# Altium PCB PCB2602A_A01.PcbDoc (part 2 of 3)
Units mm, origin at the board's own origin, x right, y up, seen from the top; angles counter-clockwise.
Board outline 30.4 x 45.4 mm, 8 copper layers (Top Layer, Signal Layer 2, Signal Layer 3, Signal Layer 4, Signal Layer 5, Signal Layer 6, Signal Layer 7, Bottom Layer), stack 1.594 mm thick; 180 components, 124 nets, 679 pads, 487 vias.
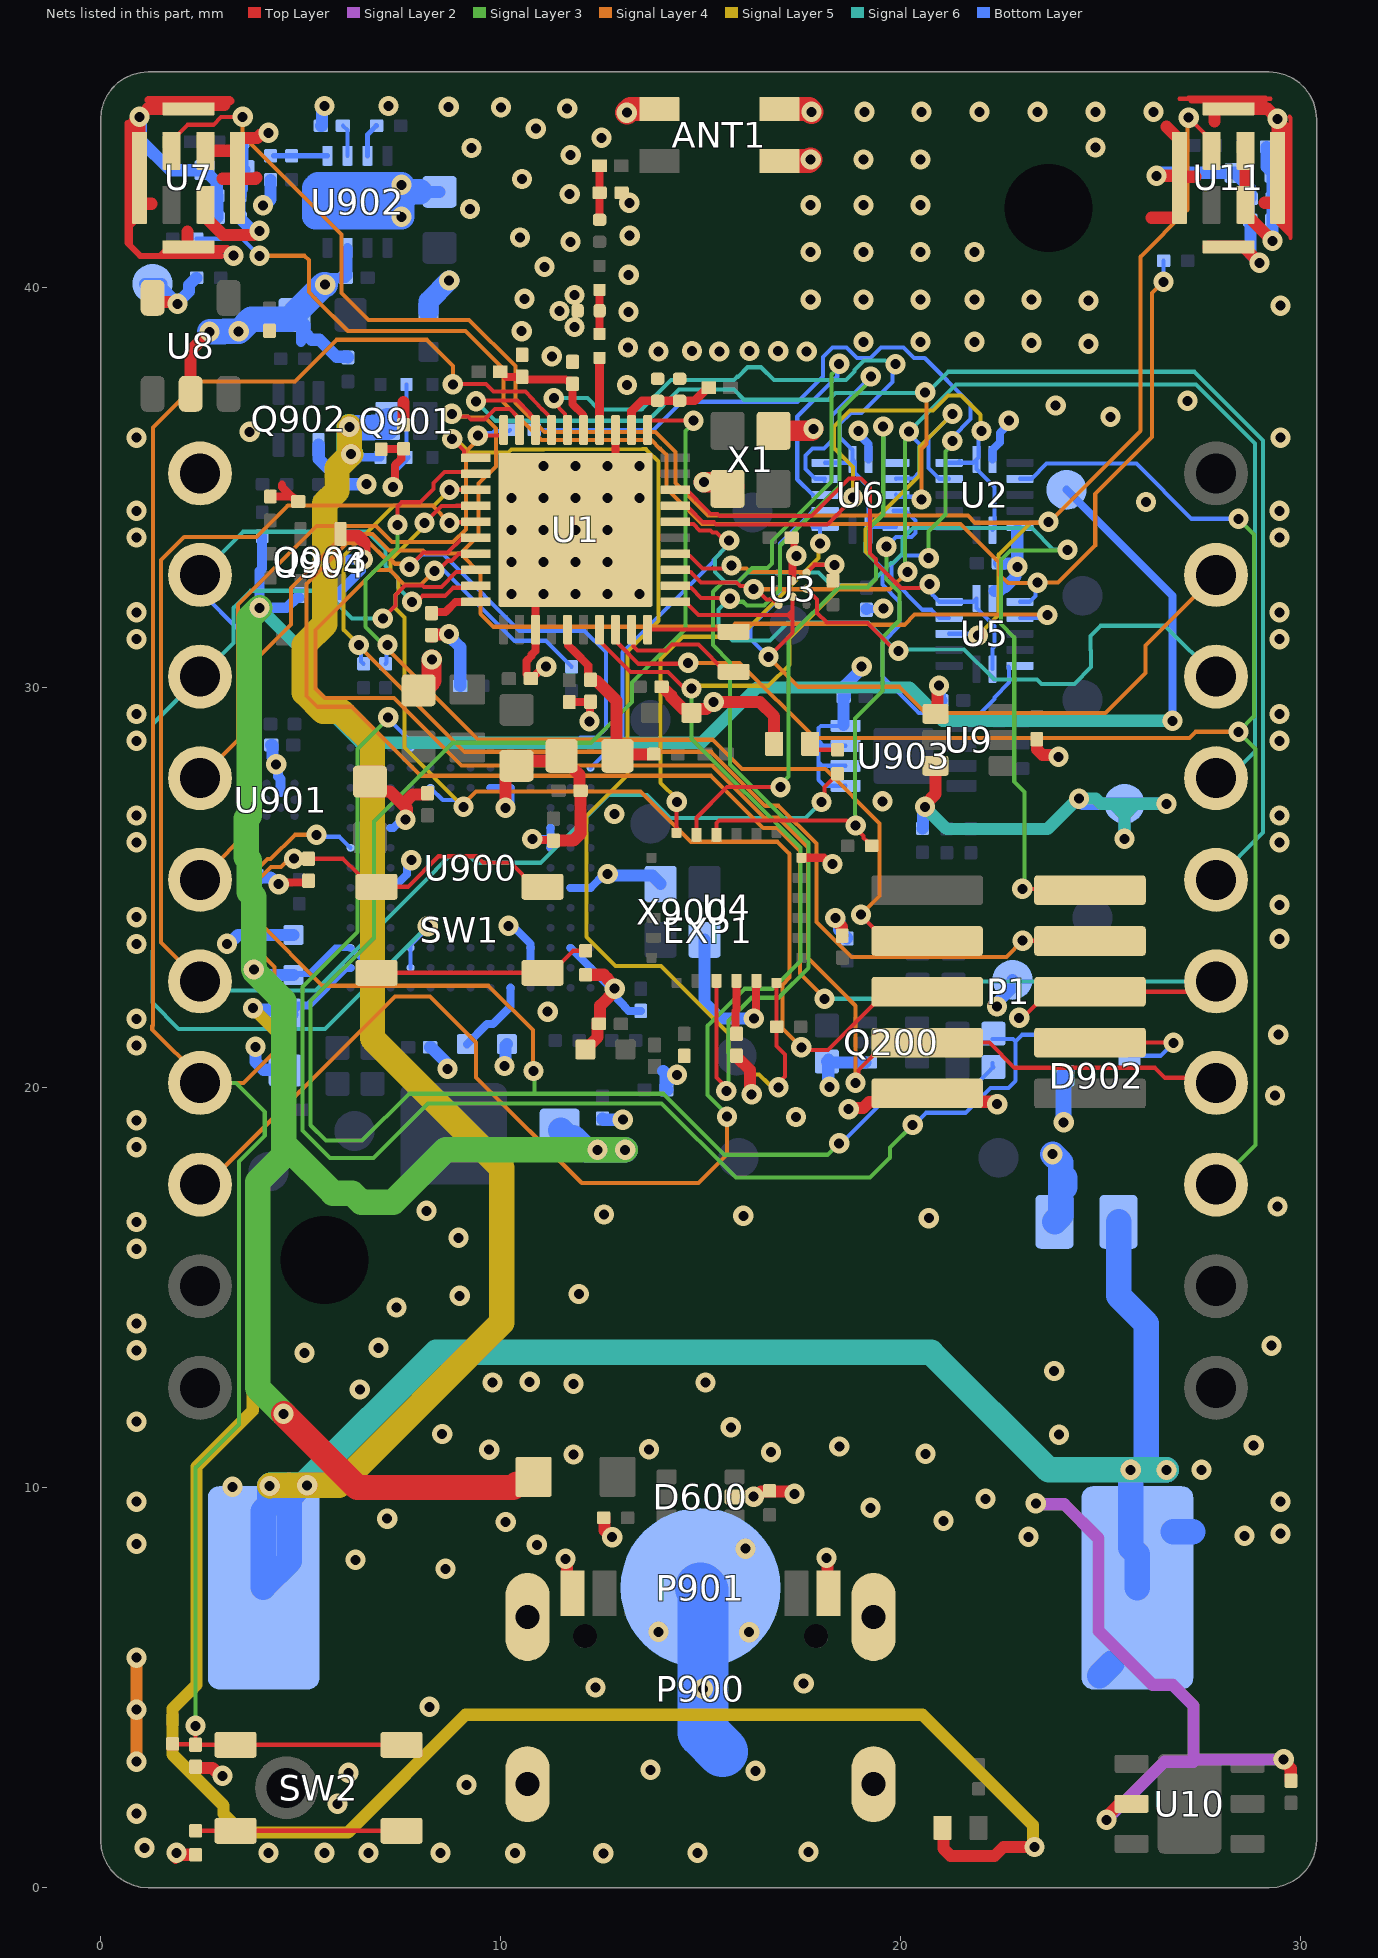
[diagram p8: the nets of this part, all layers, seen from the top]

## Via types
v1: diameter 0.508, hole 0.25, Top Layer to Bottom Layer, tented both sides, 475 vias
v2: diameter 0.5, hole 0.25, Top Layer to Bottom Layer, tented both sides, 12 vias

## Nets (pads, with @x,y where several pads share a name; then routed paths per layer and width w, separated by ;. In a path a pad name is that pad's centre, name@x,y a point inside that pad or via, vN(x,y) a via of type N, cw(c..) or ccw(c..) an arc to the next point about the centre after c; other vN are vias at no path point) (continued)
DBG_PTI_FRAME: P1.9 U1.6 U900.N2 | length 31.9
  Top Layer w0.102: U1.6@14.37,34.15 14.429,34.091 14.822,34.091 14.978,33.934 15.252,33.934 15.303,33.883 15.402,33.883 15.605,33.68 v1(15.715,33.68) ; v1(23.045,24.972) 25.053,24.972 P1.9@25.085,24.94
  Signal Layer 3 w0.102: v1(23.045,24.972) 23.104,25.031 23.104,27.396 22.841,27.659 22.841,31.263 22.512,31.592 22.512,33.193 22.75,33.432 23.982,33.432 v1@24.025,33.475
  Signal Layer 6 w0.102: v1(15.715,33.68) 15.715,33.588 15.49,33.363 15.49,33.359 15.359,33.228 15.359,32.896 15.62,32.635 15.925,32.635 16.171,32.881 17.943,32.881 18.256,32.568 19.213,32.568 19.764,33.119 19.812,33.119 20.05,33.357 20.05,33.73 20.313,33.993 23.282,33.993 23.825,33.45 v1(24.175,33.45)
  Bottom Layer w0.102: U900.N2@12.25,28 13.054,28.804 13.054,30.729 13.054,30.887 14.193,32.026 ; 14.193,32.027 15.329,33.162 15.329,33.198 15.49,33.359 15.49,33.371 15.715,33.596 v1(15.715,33.68)
DBG_RESET: D902.1 P1.3 R206.1 R209.2 U900.D1 | length 40.5
  Top Layer w0.1: v1@26.82,21.13 v1(26.825,21.125)
  Top Layer w0.102: P1.3@25.085,21.13 v1@26.82,21.13
  Signal Layer 3 w0.102: v1(7.192,29.26) 7.192,29.231 6.425,28.464 6.425,23.9 5.05,22.525 5.05,18.928 5.732,18.246 6.821,18.246 8.184,19.609 14.029,19.609 15.881,17.756 19.238,17.756 19.732,18.251 19.732,18.502 v1(20.305,19.074)
  Bottom Layer w0.102: v1(7.192,29.26) 7.192,29.231 7.75,28.672 U900.D1@7.75,28.5 ; v1(20.305,19.074) 20.33,19.074 20.631,19.375 21.623,19.375 22.246,19.998 22.698,19.998 22.875,20.175 22.875,21.162 ; R209.2@22.298,21.222 22.815,21.222 22.875,21.162 ; v1(26.825,21.125) 26.5,20.8 D902.1@25.725,20.8 25.2,21.325 23.038,21.325 22.875,21.162
DBG_SWCLK: P1.8 R920.2 U1.22 | length 25.6
  Top Layer w0.102: v1(7.425,34.075) 7.425,34.537 7.525,34.637 7.987,34.637 8.319,34.969 8.319,35.118 8.599,35.399 9.331,35.399 U1.22@9.38,35.35 ; v1(19.012,24.327) 19.012,24.31 19.653,23.67 P1.8@20.665,23.67
  Signal Layer 3 w0.102: v1(7.175,31.075) 7.068,31.075 6.619,31.525 6.619,32.693 7.425,33.5 v1(7.425,34.075)
  Signal Layer 4 w0.102: v1(7.175,31.075) 7.175,30.968 9.443,28.7 15.306,28.7 16.039,27.967 18.119,27.967 19.475,26.611 19.475,24.789 v1(19.012,24.327)
  Bottom Layer w0.102: R920.2@7.125,30.6 7.15,30.625 7.15,31.05 v1(7.175,31.075)
DBG_SWDIO: P1.7 R919.2 U1.23 | length 29.7
  Top Layer w0.102: v1(8.725,34.95) U1.23@9.38,34.95 ; v1(23.053,23.676) 24.729,23.676 P1.7@24.735,23.67
  Signal Layer 4 w0.102: v1(6.455,31.069) 6.455,31.045 9.1,28.4 15.267,28.4 16.617,27.05 16.95,27.05 17.893,26.107 17.893,24.145 18.772,23.266 22.643,23.266 v1(23.053,23.676)
  Signal Layer 5 w0.102: v1(6.455,31.069) 6.074,31.451 6.074,33.298 6.618,33.843 7.332,34.556 8.331,34.556 v1(8.725,34.95)
  Bottom Layer w0.102: v1(6.455,31.069) 6.515,31.01 6.515,30.66 R919.2@6.575,30.6
DBG_SWO: P1.6 U1.24 U900.E3 | length 28.6
  Top Layer w0.102: v1(8.1,34.125) 8.519,34.544 8.893,34.544 8.9,34.55 U1.24@9.38,34.55 ; v1(17.517,21.009) 17.579,20.948 18.188,20.948 18.96,21.72 19.64,22.4 P1.6@20.665,22.4
  Signal Layer 4 w0.102: v1@9.037,27.063 9.381,27.406 13.501,27.406 14.757,26.15 16.925,26.15 17.225,25.85 17.225,22.755 17.044,22.574 17.044,21.483 v1(17.517,21.009)
  Signal Layer 5 w0.102: v1(8.1,34.125) 8.1,34.05 7.244,33.194 7.244,32.931 7.318,32.856 7.318,32.855 7.45,32.723 7.45,32.388 7.379,32.317 7.379,31.98 7.598,31.761 7.598,29.062 7.595,29.059 7.595,28.505 v1(9.075,27.025)
  Bottom Layer w0.102: U900.E3@8.25,27.5 8.555,27.195 8.905,27.195 v1(9.075,27.025)
DBG_VBUS: C901.1 D901.2 L901.2 R917.1 TPJ12.1 U900.A11 U900.B12 U904.5 | length 78.6
  Top Layer w0.635: v1(4.575,11.85) 6.418,10.007 10.321,10.007 10.406,10.092 10.692,10.092 10.825,10.225 L901.2@10.825,10.275
  Signal Layer 3 w0.635: v1(3.975,32) 3.718,31.743 3.718,26.805 3.643,26.731 3.643,25.767 3.718,25.693 3.718,24.891 3.833,24.776 v1(3.833,22.958) 3.85,22.975 3.85,22.902 4.575,22.177 4.575,18.3 3.928,17.654 3.928,12.497 v1(4.575,11.85) ; 4.725,18.45 5.808,17.367 6.291,17.367 6.517,17.141 7.316,17.141 8.625,18.45 v1(12.425,18.45) 12.427,18.448 v1(13.117,18.448)
  Signal Layer 6 w0.305: v1(3.975,32) 5,30.975 5,30.117 6.492,28.625 15.026,28.625 16,29.599 16,29.6 16.408,30.008 20.223,30.008 21.056,29.175 v1(26.8,29.175)
  Bottom Layer w0.152: C901.1@4.824,22.822 4.85,22.848 5.214,22.848 5.866,23.5 U900.A11@6.25,23.5 U900.B12@6.75,23
  Bottom Layer w0.203: TPJ12.1@24.15,34.95 26.8,32.3 v1(26.8,29.175)
  Bottom Layer w0.254: R917.1@4.04,33.787 4.04,32.98 3.975,32.915 v1(3.975,32) 4.65,32 4.902,32.252 U904.5@4.973,32.252
  Bottom Layer w0.305: v1(3.833,22.958) 3.888,22.958 4.025,22.822 C901.1@4.824,22.822
  Bottom Layer w0.635: D901.2@11.5,18.94 11.683,18.758 11.817,18.758 12.125,18.45 v1(12.425,18.45) 12.427,18.448 v1(13.117,18.448)
DBG_VCOM_CTS: EXP1.3 R922.2 U1.29 | length 10.7
  Top Layer w0.102: v1(7.785,32.148) 7.895,32.148 8.047,32.3 8.607,32.3 8.807,32.5 9.33,32.5 U1.29@9.38,32.55
  Signal Layer 6 w0.102: EXP1.3@2.486,32.82 3.566,33.9 6.675,33.9 7.125,33.45 7.125,33.046 7.432,32.74 7.432,32.502 v1(7.785,32.148)
  Bottom Layer w0.102: EXP1.3@2.486,32.82 2.486,32.415 3.5,31.401 R922.2@3.776,31.401
DBG_VCOM_RTS: EXP1.5 U1.28 U900.D11 U900.D12 | length 27.4
  Top Layer w0.102: v1(7.056,31.733) 7.375,32.053 7.375,32.314 7.616,32.555 8.049,32.555 8.086,32.518 8.518,32.518 8.891,32.891 9.321,32.891 U1.28@9.38,32.95
  Signal Layer 6 w0.102: v1(7.056,31.733) 6.287,31.733 5.596,32.425 3.75,32.425 3.325,32 3.325,31.119 EXP1.5@2.486,30.28 1.307,29.101 1.307,23.427 1.3,23.42 1.3,22.128 1.954,21.474 5.612,21.474 v1(8.176,24.038)
  Bottom Layer w0.102: U900.D12@7.75,23 U900.D11@7.75,23.5 7.75,23.562 v1@8.226,24.038
DBG_VCOM_RX: EXP1.14 P1.4 R921.2 U1.27 | length 41.2
  Top Layer w0.102: v1(8.35,32.925) 8.426,32.925 8.676,33.175 8.775,33.175 8.95,33.35 U1.27@9.38,33.35 ; v1(18.875,20.125) 18.953,20.202 18.953,20.443 19.64,21.13 22.22,21.13 22.85,20.5 26.366,20.5 26.616,20.25 27.756,20.25 EXP1.14@27.886,20.12
  Signal Layer 4 w0.102: 6.8,32.875 5.368,31.443 5.368,29.982 5.607,29.743 7.338,29.743 9.025,28.056 15.291,28.056 16.598,26.75 16.95,26.75 17.69,26.01 17.69,23.239 18.481,22.447 18.481,22.444 18.875,22.051 v1@18.875,20.127 ; 6.803,32.872 6.872,32.94 7.231,32.94 7.586,32.585 8.01,32.585 v1(8.35,32.925)
  Bottom Layer w0.102: v1@8.475,33.05 10.35,31.175 11.135,31.175 11.775,30.535 R921.2@11.775,30.525
DBG_VCOM_TX: EXP1.12 P1.5 U1.26 U900.L2 U900.M1 | length 50.9
  Top Layer w0.102: v1(7.725,33.023) 7.725,33.025 8.079,33.379 8.679,33.379 9.05,33.75 U1.26@9.38,33.75 ; v1(22.967,21.749) 23.046,21.749 23.698,22.4 27.626,22.4 EXP1.12@27.886,22.66
  Signal Layer 4 w0.102: v1(7.725,33.023) 7.647,33.101 7.358,33.101 7.233,33.226 7.117,33.226 6.728,33.615 6.165,33.615 5.15,32.6 5.15,29.8 5.425,29.525 6.281,29.525 8.006,27.8 15.26,27.8 16.567,26.493 16.907,26.493 17.486,25.914 17.486,22.853 18.1,22.239 v1(18.1,22.225)
  Signal Layer 6 w0.102: v1(18.1,22.225) 19.762,22.225 20.197,22.66 EXP1.12@27.886,22.66
  Bottom Layer w0.102: v1(7.725,33.023) 7.725,33.025 8.032,33.332 8.568,33.332 8.732,33.168 10.475,31.425 12.1,31.425 12.632,30.893 12.632,28.982 12.403,28.753 12.003,28.753 U900.M1@11.75,28.5 U900.L2@11.25,28
DBG_VREGO: C902.1 LED900.1 U900.A12 | length 51.6
  Top Layer w0.3: LED900.1@21.05,1.5 21.074,1.476 21.074,0.976 21.25,0.8 22.351,0.8 22.568,1.018 v1(23.35,1.018)
  Signal Layer 5 w0.3: 22.187,2.687 23.31,1.565 23.31,1.057 v1(23.35,1.018)
  Signal Layer 5 w0.305: v1(3.809,21.991) 4.7,21.1 4.7,18.425 3.805,17.53 3.805,11.93 2.4,10.525 2.4,5.075 1.8,4.475 1.8,3.331 3.075,2.056 3.075,1.85 3.542,1.383 6.183,1.383 9.125,4.325 20.55,4.325 22.187,2.687
  Bottom Layer w0.2: C902.1@4.8,21.833 4.8,21.903 4.95,22.053 5.195,22.053 6.142,23 U900.A12@6.25,23
  Bottom Layer w0.305: v1(3.809,21.991) 3.848,21.952 4.506,21.952 C902.1@4.625,21.833 C902.1@4.8,21.833
EFR32_BUTTON0: C38.1 EXP1.13 R25.2 SW2.1 SW2.2 U1.17 U900.A6 | length 63.3
  Top Layer w0.1: v1(8.806,37.588) 9.637,37.588 9.819,37.406 10.62,37.406 11.035,36.964 ccw(c11.331,37.241) 11.045,36.953 11.156,36.843 11.215,36.784 11.215,36.505 U1.17@11.275,36.445
  Top Layer w0.102: R25.2@1.8,3.6 1.812,3.588 2.362,3.588 C38.1@2.375,3.575 ; v1(2.375,4.05) C38.1@2.375,3.575 ; SW2.2@7.525,3.575 SW2.1@3.375,3.575 C38.1@2.375,3.575
  Signal Layer 3 w0.102: v1(2.375,4.05) 2.375,10.5 3.459,11.584 3.459,18.159 4.105,18.805 4.105,19.395 3.38,20.12 EXP1.13@2.486,20.12
  Signal Layer 4 w0.102: v1(5.4,26.325) 4.858,26.325 4.252,25.719 4.176,25.719 3.675,25.218 3.675,23.691 4.35,23.016 4.35,20.9 3.57,20.12 EXP1.13@2.486,20.12 2.486,20.264 1.292,21.458 1.292,21.542 1.306,21.557 1.306,36.504 2.458,37.656 4.857,37.656 5.902,38.7 7.811,38.7 8.157,38.7 8.812,38.045 8.812,37.594 v1(8.806,37.588)
  Bottom Layer w0.102: v1@5.4,26.275 5.975,26.275 U900.A6@6.25,26
EFR32_I2C_SCL: EXP1.15 U1.37 U2.4 | length 48.6
  Top Layer w0.102: U1.37@12.475,31.17 13.248,30.397 14.185,30.397 14.357,30.225 14.648,29.934 14.728,29.934 v1(14.775,29.981)
  Signal Layer 3 w0.102: v1(14.775,29.981) 14.775,28.725 17.496,26.004 17.496,23.171 16.8,22.475 16.1,22.475 15.175,21.55 15.175,19.815 15.66,19.331 v1(15.66,19.277)
  Signal Layer 4 w0.102: EXP1.15@2.486,17.58 2.655,17.58 7.356,22.281 8.238,22.281 9.382,21.137 9.382,20.262 12.029,17.614 14.944,17.614 15.66,18.33 v1(15.66,19.277)
  Signal Layer 5 w0.102: v1(14.775,29.981) 14.845,30.051 16.701,30.051 17.225,30.575 17.225,31.25 18.525,32.55 19.212,32.55 19.381,32.719 19.381,33.143 19.334,33.19 19.334,33.194 19.125,33.403 19.125,33.953 20.475,35.303 20.475,36.025 v1(21.298,36.848)
  Bottom Layer w0.102: v1(14.775,29.981) 14.775,30.025 v1@14.8,30.05 ; U2.4@21.215,35.225 20.975,35.225 20.827,35.373 20.824,35.373 20.7,35.496 20.7,36.25 v1(21.298,36.848)
EFR32_I2C_SDA: EXP1.16 U1.38 U2.9 | length 40.4
  Top Layer w0.102: U1.38@12.875,31.176 13.013,31.038 13.451,30.6 14.667,30.6 v1(14.691,30.624)
  Signal Layer 3 w0.102: EXP1.16@27.886,17.58 28.875,18.569 28.875,28.475 v1(28.45,28.9) 28.838,29.288 28.838,33.837 v1(28.45,34.225)
  Signal Layer 4 w0.102: v1(14.691,30.624) 15.976,30.624 17.856,28.744 27.219,28.744 27.375,28.9 v1(28.45,28.9)
  Bottom Layer w0.102: U2.9@22.985,35.225 23.275,35.225 23.652,35.602 25.898,35.602 27.275,34.225 v1(28.45,34.225)
EFR32_IMU_ENABLE: U1.16 U5.12 U6.5 U6.6 U6.12 U6.13 | length 25.5
  Top Layer w0.102: v1(11.331,37.241) 11.331,37.131 11.616,36.846 11.616,36.504 U1.16@11.675,36.445
  Signal Layer 6 w0.102: v1(11.331,37.241) 12.172,37.241 12.452,36.961 13.529,36.961 14.262,37.694 15.834,37.694 15.915,37.775 15.938,37.775 16.176,38.013 16.513,38.013 16.832,37.694 18.634,37.694 18.849,37.909 18.849,37.949 19.087,38.187 19.613,38.187 19.631,38.168 19.798,38.168 v1(19.875,38.091)
  Bottom Layer w0.102: U6.5@18.115,35.625 U6.6@18.751,35.625 ; U6.6@18.8,35.71 18.8,35.95 18.49,36.26 18.49,36.602 18.763,36.875 19.025,36.875 19.798,37.648 19.798,38.013 v1(19.875,38.091) ; U6.6@18.805,35.705 18.849,35.661 18.849,35.376 19.217,35.008 19.217,34.597 19.2,34.58 U6.13@19.2,33.976 ; U6.12@19.885,34.025 19.249,34.025 U6.13@19.2,33.976 ; U5.12@22.7,30.525 22.716,30.509 22.716,30.128 22.346,29.759 22.346,29.722 21.997,29.372 20.455,29.372 19.544,30.284 19.544,31.125 19.975,31.556 19.975,32.15 19.544,32.581 19.544,32.984 19.125,33.403 19.125,33.625 19.2,33.7 U6.13@19.2,33.976
EFR32_IMU_INT: R14.2 U1.21 U4.12 | length 28.2
  Top Layer w0.1: v1(8.788,36.22) 9.081,35.927 9.081,35.81 9.141,35.75 U1.21@9.38,35.75
  Top Layer w0.102: U4.12@16.9,22.53 R14.2@16.9,21.525 16.9,21.046 17.111,20.835 17.111,20.283 16.948,20.12 v1(16.948,20.01)
  Signal Layer 5 w0.1: v1(8.788,36.22) 8.89,36.22 9.223,35.888 10.201,35.888 10.269,35.956 11.073,35.956 13.55,35.966 13.633,35.966 13.663,35.937 13.945,35.655
  Signal Layer 5 w0.102: 13.945,35.655 13.945,31.675 13.175,30.905 13.175,27.825 12.15,26.8 12.15,23.775 12.877,23.048 14.006,23.048 15.7,21.354 15.7,20.875 16.244,20.331 16.463,20.331 16.706,20.088 16.87,20.088 v1(16.948,20.01)
EFR32_LED0: EXP1.11 R27.1 U1.25 | length 39
  Top Layer w0.102: v1(8.725,34.125) 8.737,34.137 9.367,34.137 U1.25@9.38,34.15 ; v1(18.023,27.143) 18.1,27.221 18.1,27.515 18.425,27.84 R27.1@18.425,27.85
  Signal Layer 4 w0.102: EXP1.11@2.486,22.66 1.51,23.636 1.51,33.191 2.091,33.772 3.896,33.772 4.68,34.556 8.294,34.556 v1(8.725,34.125)
  Signal Layer 6 w0.102: EXP1.11@2.891,22.66 EXP1.11@2.486,22.66 2.713,22.433 5.292,22.433 5.377,22.433 8.385,25.441 8.385,25.46 8.713,25.788 9.237,25.788 9.4,25.625 10.995,25.625 12.694,27.324 13.657,27.324 14.238,26.744 17.624,26.744 v1(18.023,27.143)
EFR32_MIC_ENABLE: U1.8 U5.5 U5.6 U5.13 | length 12.9
  Top Layer w0.102: U1.8@14.37,34.95 14.429,34.891 14.709,34.891 14.893,34.707 14.893,34.691 15.243,34.341 15.42,34.341 15.472,34.29 17.77,34.29 18.712,35.232 19.015,35.232 19.237,35.01 19.237,33.357 19.382,33.213 19.382,33.118 19.768,32.732 20.007,32.493 20.464,32.493 20.481,32.511 20.649,32.511 v1(20.726,32.588)
  Signal Layer 4 w0.102: v1@20.614,32.511 20.632,32.493 v1(20.726,32.588)
  Bottom Layer w0.1: v1(20.726,32.588) 20.804,32.51 20.804,32.323 20.852,32.276
  Bottom Layer w0.102: 20.852,32.276 20.978,32.15 U5.5@21.215,32.15 21.815,32.15 U5.6@21.9,32.235 21.9,31.991 22.35,31.541 22.35,31.028 22.3,30.978 U5.13@22.3,30.465
EFR32_PB0: EXP1.7 R16.2 U1.20 | length 15.6
  Top Layer w0.1: v1(9.43,36.302) 10.015,36.302 10.015,36.305 10.075,36.365 U1.20@10.075,36.445
  Signal Layer 4 w0.1: EXP1.7@2.486,27.74 3.438,28.692 3.438,32.08 5.402,34.045 6.021,34.045 6.881,34.045 7.287,33.639 8.813,33.639 9.131,33.957 9.131,35.902 9.43,36.202 v1(9.43,36.302)
  Bottom Layer w0.1: v1(9.43,36.302) 9.5,36.372 9.798,36.372 9.851,36.424 10.216,36.424 R16.2@10.241,36.449
EFR32_PC0: EXP1.4 U1.1 U3.D2 U6.2 | length 22.9
  Top Layer w0.102: U1.1@14.605,32.175 14.689,32.091 14.689,32.077 14.949,31.818 17.183,31.818 ; v1(16.7,30.775) 17.3,31.375 17.3,31.7 ; U3.D2@17.3,32.275 17.3,31.935 ; 17.183,31.818 17.3,31.7 ; 17.183,31.818 17.3,31.935 ; 17.3,31.7 17.3,31.935
  Signal Layer 4 w0.102: v1(16.7,30.775) 17.45,30.025 19.975,30.025 20.628,29.372 25.127,29.372 26.125,30.371 26.125,31.059 EXP1.4@27.886,32.82
  Bottom Layer w0.102: v1(16.7,30.775) 16.25,31.225 16.25,31.523 16.758,32.031 ; 16.759,32.032 16.985,32.257 16.985,33.605 U6.2@17.805,34.425
EFR32_PC1: EXP1.6 U1.2 U3.C3 U6.4 | length 32.1
  Top Layer w0.102: U1.2@14.37,32.55 14.429,32.491 14.773,32.491 15.016,32.247 15.711,32.247 v1(15.73,32.228) ; U3.C3@17.65,32.475 17.916,32.209 17.916,31.873 18.155,31.633 19.167,31.633 19.875,30.925 v1(19.95,30.925)
  Signal Layer 3 w0.102: v1(15.73,32.228) 15.808,32.151 16.066,32.151 16.16,32.057 16.592,32.057 16.985,32.45 16.985,33.551 18.478,35.044 18.478,36.919 19.256,37.696 v1(19.256,37.78)
  Signal Layer 6 w0.102: v1(15.73,32.228) 15.725,32.228 15.45,31.953 15.45,31.525 15.794,31.181 16.731,31.181 17.175,31.625 19.2,31.625 19.9,30.925 v1(19.95,30.925) 19.981,30.956 21.59,30.956 22.343,30.204 23.416,30.204 23.522,30.098 24.348,30.098 24.765,30.515 24.765,30.927 24.745,30.947 24.745,31.295 25,31.55 26.616,31.55 EXP1.6@27.886,30.28
  Bottom Layer w0.102: U6.4@18.052,35.218 18.094,35.176 U6.4@18.098,35.176 ; U6.4@18.115,35.225 17.875,35.225 17.727,35.373 17.724,35.373 17.623,35.474 17.623,35.805 17.8,35.982 18.082,35.982 18.287,36.187 18.287,36.811 v1(19.256,37.78)
EFR32_PD0: U1.40 X2.1 | length 2.2
  Top Layer w0.102: U1.40@13.675,31.455 14.825,31.455 15.773,31.455 X2.1@15.828,31.4
EFR32_PD1: U1.39 X2.2 | length 3.3
  Top Layer w0.102: U1.39@13.275,31.455 13.325,31.405 13.325,31.028 13.42,30.933 14.138,30.933 14.284,31.079 14.949,31.079 15.628,30.4 X2.2@15.828,30.4
EFR32_PDM_CLK: R16.1 U5.4 | length 20.5
  Signal Layer 3 w0.102: v1(20.702,33.238) 20.702,33.91 21.125,34.333 21.125,35.908 21.294,36.076 v1(21.294,36.17)
  Bottom Layer w0.102: R16.1@10.841,36.449 12.875,36.449 13.824,36.449 14.525,37.15 17.425,37.15 18.059,37.784 18.059,38.268 18.297,38.506 18.644,38.506 18.907,38.244 19.243,38.244 19.506,38.507 20.069,38.507 20.332,38.244 20.604,38.244 21.752,37.096 21.752,36.719 21.294,36.261 v1(21.294,36.17) ; v1@20.626,33.238 v1(20.702,33.238) 20.634,33.306 20.007,33.306 19.769,33.068 19.769,32.731 20.55,31.95 20.771,31.95 20.971,31.75 U5.4@21.215,31.75
EFR32_PDM_DATA: EXP1.9 U1.19 U5.9 | length 37.1
  Top Layer w0.1: 9.86,36.967 10.241,36.967 10.337,36.871 10.337,36.853 10.415,36.774 10.415,36.505 U1.19@10.475,36.445
  Top Layer w0.102: v1(8.783,36.85) 8.849,36.783 9.189,36.783 9.264,36.708 9.602,36.708 9.86,36.967
  Signal Layer 4 w0.102: EXP1.9@2.486,25.2 3.9,26.614 3.9,30.725 4.76,31.585 4.76,32.498 6.105,33.843 6.797,33.843 7.211,33.429 8.066,33.429 8.139,33.356 8.994,33.356 ; v1(8.783,36.85) 8.849,36.783 9.189,36.783 9.22,36.753 9.615,36.753 9.882,36.486 9.882,35.535 9.45,35.102 9.45,33.813 8.994,33.356 ; v1(23.669,31.819) 23.66,31.829 20.354,31.829 20.101,31.575 19.218,31.575 19.193,31.6 15.859,31.6 15.784,31.525 9.825,31.525 9.5,31.85 9.5,32.85 8.994,33.356
  Bottom Layer w0.102: U5.9@22.985,31.75 23.6,31.75 v1(23.669,31.819)
EFR32_RESET: C1.1 R209.1 R212.2 SW1.1 SW1.2 U1.11 | length 63.5
  Top Layer w0.102: v1(4.834,25.727) C1.1@5.199,25.726 ; C1.1@5.2,25.725 6.061,25.725 6.435,25.351 6.435,25.298 6.708,25.025 SW1.1@6.9,25.025 7.685,25.025 8.448,25.788 9.403,25.788 9.559,25.632 10.243,25.632 10.85,25.025 SW1.2@11.05,25.025 SW1.2@11.3,24.775 ; U1.11@13.675,36.445 13.675,36.617 13.734,36.677 v1(14.823,36.677)
  Signal Layer 3 w0.102: v1(10.823,20.421) 10.85,20.395 10.85,19.85 ; v1(14.823,36.677) 14.823,36.617 14.62,36.414 14.62,31.471 13.284,30.134 13.284,29.643 12.266,28.625 8.796,28.625 6.83,26.66 6.83,23.743 5.253,22.166 5.253,19.063 5.637,18.679 6.536,18.679 7.707,19.85 10.808,19.85 10.85,19.85 ; v1(18.464,18.61) 18.459,18.61 18.174,18.325 15.6,18.325 14.075,19.85 10.85,19.85
  Signal Layer 4 w0.102: v1(4.834,25.727) 4.724,25.727 4.513,25.516 4.261,25.516 3.936,25.191 3.936,24.164 5.55,22.55 9.7,22.55 10.808,21.442 10.808,20.437 v1(10.823,20.421)
  Bottom Layer w0.102: v1(18.464,18.61) 18.509,18.61 19.649,19.75 21.557,19.75 22.25,20.443 R212.2@22.25,20.45 ; R212.2@22.298,20.622 22.298,20.498 22.314,20.514 R212.2@22.321,20.514
EFR32_SENSOR_ENABLE: U1.7 U2.5 U2.6 U2.13 | length 15.1
  Top Layer w0.102: U1.7@14.37,34.55 14.429,34.491 14.709,34.491 15.062,34.138 15.336,34.138 15.387,34.086 18.168,34.086 18.811,34.729 v1(18.811,34.755)
  Signal Layer 5 w0.102: v1(18.811,34.755) 18.811,35.521 18.331,36 18.331,36.531 18.737,36.937 20.812,36.937 21.183,37.308 21.517,37.308 22,36.825 22,36.444 v1(22.025,36.418)
  Bottom Layer w0.102: U2.5@21.215,35.625 21.815,35.625 U2.6@21.9,35.71 ; U2.5@21.425,35.625 U2.5@21.474,35.674 ; v1@22.025,36.327 v1(22.025,36.418) 21.949,36.342 21.949,35.759 U2.6@21.9,35.71 ; U2.13@22.3,33.94 22.35,33.99 22.35,35.016 21.9,35.466 U2.6@21.9,35.71
EFR32_SPI_FLASH_CS: R12.2 U1.4 U3.A3 | length 5.6
  Top Layer w0.102: U1.4@14.37,33.35 14.429,33.291 14.733,33.291 15.044,32.98 15.695,32.98 v1(15.772,33.057) ; U3.A3@17.65,32.875 17.85,33.075 v1(18.35,33.075) v1@18.375,33.075
  Top Layer w0.203: R12.2@18.307,32.685 R12.2@18.312,32.68 ; v1@18.355,33.07 v1(18.35,33.075) 18.331,33.056 18.331,32.699 R12.2@18.312,32.68 ; R12.2@18.37,32.611 18.312,32.67 R12.2@18.312,32.68
  Signal Layer 4 w0.102: v1(15.772,33.057) 15.85,32.98 16.144,32.98 16.23,32.893 17.643,32.893 17.824,33.075 v1(18.35,33.075)
EFR32_SPI_IMU_CS: EXP1.10 U1.18 U6.10 | length 38.2
  Top Layer w0.1: v1(9.388,37.159) 9.409,37.18 10.418,37.18 10.737,36.862 10.737,36.843 10.875,36.705 U1.18@10.875,36.445
  Signal Layer 4 w0.102: v1(20.521,34.708) 20.521,35.97 20.645,36.093 20.645,37.355 v1(20.615,37.385)
  Signal Layer 6 w0.102: v1(9.388,37.159) 9.872,36.675 13.68,36.675 14.459,37.455 15.832,37.455 16.086,37.2 18.203,37.2 18.377,37.374 20.604,37.374 v1(20.615,37.385) ; v1@20.645,37.355 21.189,37.9 27.35,37.9 29.066,36.184 29.066,26.38 EXP1.10@27.886,25.2
  Bottom Layer w0.102: U6.10@19.885,34.825 19.934,34.776 20.454,34.776 v1(20.521,34.708)
EFR32_SPI_SCLK: EXP1.8 U1.3 U3.E1 U6.9 | length 31.1
  Top Layer w0.102: U1.3@14.37,32.95 14.429,32.891 14.754,32.891 15.01,32.635 15.899,32.635 15.993,32.541 16.251,32.541 v1(16.329,32.463) ; v1@16.33,32.462 16.4,32.462 16.651,32.211 16.814,32.211 U3.E1@16.989,32.036
  Signal Layer 3 w0.102: v1(20.175,32.9) 20.115,32.96 20.115,36.2 20.209,36.295 v1(20.209,36.405)
  Signal Layer 4 w0.102: v1(16.329,32.463) 19.738,32.463 v1(20.175,32.9)
  Signal Layer 6 w0.102: v1(16.329,32.463) v1@16.344,32.448 ; v1(20.209,36.405) 21.386,37.581 27.381,37.581 28.856,36.106 28.856,28.407 28.19,27.74 EXP1.8@27.886,27.74
  Bottom Layer w0.102: U6.9@19.885,35.225 19.892,35.232 20.318,35.232 20.475,35.389 20.475,36.095 20.209,36.361 v1(20.209,36.405)
GND: ANT1.2 ANT1.3 ANT1.4 C1.2 C2.2 C4.2 C7.2 C8.2 C9.2 C11.2 C12.2 C13.2 C14.2 C15.2 C16.2 C18.2 C19.2 C20.2 C21.2 C22.2 C23.2 C24.2 C25.2 C26.2 C27.2 C28.2 C29.2 C30.2 C31.2 C32.2 C33.2 C34.2 C35.2 C36.2 C37.2 C38.2 C39.2 C900.2 C901.2 C902.2 C903.2 C904.2 C905.2 C907.2 C908.2 C909.2 C910.2 C911.2 C914.2 C915.2 C916.2 C917.2 C918.2 C919.2 C920.2 C921.2 C923.2 C924.2 C925.2 C926.2 C928.2 D600.2 D902.3 EXP1.1 LED1.2 P1.2 P900.A1_B12 P900.B1_A12 P900.S1 P900.S2 P900.S3 P900.S4 P901.2 Q200.1 Q902.1 Q903.1 R1.1 R26.2 R208.1 R620.1 R621.1 R909.1 R915.1 R933.2 R934.2 R937.2 TPJ13.1 U1.0 U1.13 U1.33 U2.7 U2.12 U3.B2 U4.11 U4.18 U5.7 U6.7 U7.3 U7.5 U7.6 U7.7 U7.8 U8.2 U9.1 U10.2 U11.5 U11.6 U11.7 U11.8 U900.C5 U900.C8 U900.H3 U900.J3 U900.K11 U900.K12 U900.L5 U900.L6 U900.M8 U900.M11 U900.N8 U900.N12 U901.B2 U902.3 U902.9 U903.1 U903.2 U903.3 U903.4 U904.2 U904.4 X1.2 X1.4 X900.2 X900.4 | length 185.4
  Top Layer w0.102: 26.975,44.725 27.175,44.725 ; 27.25,44.675 27.267,44.658 29.117,44.658 29.125,44.65 ; 29.125,44.75 27.2,44.75 27.175,44.725 ; 29.25,44.725 27.175,44.725 ; U11.8@29.412,41.638 29.75,41.3 ; 29.625,41.568 29.7,41.493 29.7,41.4 ; 29.725,44.275 29.75,44.25 29.75,41.3 ; 29.75,41.25 29.75,41.3
  Top Layer w0.15: 0.675,44.125 0.675,41.116 0.739,41.052 ; U7.6@0.975,42.75 0.975,42.16 0.975,41.788 0.739,41.551 0.739,41.052 ; U7.5@2.2,41.025 1.713,41.025 U7.5@1.556,40.869 ; 3,40.8 2.931,40.869 U7.5@1.556,40.869 ; 3.025,40.8 1.487,40.8 ; 0.739,41.052 0.991,40.8 1.487,40.8 ; 1.487,40.8 U7.5@1.556,40.869
  Top Layer w0.18: C25.2@17.275,33.75 17.335,33.69 17.335,33.36 v1(17.395,33.3)
  Top Layer w0.2: 1.2,44.7 3.225,44.7 3.25,44.675 ; v1@1.825,0.75 v1@1.875,0.7 ; U7.5@2.2,41.025 2.2,40.968 3.16,40.968 v1(3.325,40.802) ; R26.2@2.35,0.825 R26.2@2.375,0.8 ; v1(4.454,25.089) 4.497,25.132 5.157,25.132 C1.2@5.2,25.175 ; v1(10.795,26.22) 10.815,26.199 11.301,26.199 C925.2@11.321,26.179 ; 10.875,30.925 10.778,30.828 10.778,30.799 10.65,30.671 10.65,30.338 10.678,30.31 10.678,30.29 10.738,30.23 C9.2@10.758,30.23 10.778,30.23 11.074,30.526 v1(11.141,30.526) ; U1.33@10.875,31.455 U1.0@10.875,32.95 ; C13.2@11.719,29.643 11.722,29.647 C21.2@12.247,29.647 ; v1(12.225,29.159) 12.238,29.172 12.238,29.637 C21.2@12.247,29.647 ; C21.2@12.25,29.65 C21.2@12.247,29.647 ; U1.0@12.875,35.75 U1.13@12.875,36.445 ; U3.B2@17.3,32.675 17.3,33.121 17.395,33.217 v1(17.395,33.3)
  Top Layer w0.203: R937.2@4.244,34.781 C928.2@4.773,34.781 ; 4.534,35.075 4.534,35.02 C928.2@4.773,34.781 ; C928.2@4.943,34.656 4.923,34.656 4.827,34.752 4.802,34.752 C928.2@4.773,34.781 ; 10.875,30.925 U1.33@10.875,31.455 ; v1@12.22,29.164 v1(12.225,29.159) ; ANT1.4@13.972,44.378 ANT1.4@13.986,44.378 ; v1(16.332,21.732) 16.382,21.782 16.382,22.512 U4.11@16.4,22.53 ; U4.18@17.62,25.75 18.088,25.75 v1@18.244,25.593
  Top Layer w0.3: Q903.1@6,33.85 6,33.806 6.424,33.806 6.6,33.631 6.6,33.613 ; v1(6.559,33.209) 6.599,33.249 6.599,33.612 ; R915.1@7.575,36.575 7.575,37.143 ; v1(11.622,8.222) 11.662,8.182 11.662,7.498 P900.A1_B12@11.8,7.36 ; C903.2@12.119,20.956 12.428,21.264 12.428,21.59 12.438,21.6 C905.2@12.458,21.6 12.478,21.6 12.488,21.61 12.488,22.054 12.854,22.42 v1(12.854,22.477) ; R621.1@12.575,9.25 12.585,9.25 12.595,9.24 12.595,8.936 12.766,8.766 v1(12.791,8.766) ; v1(15.328,29.645) 16.48,29.645 16.841,29.284 LED1.2@16.841,28.6 ; D600.2@15.85,9.775 15.852,9.777 16.324,9.777 v1(16.326,9.779) 16.382,9.779 16.508,9.905 16.715,9.905 R620.1@16.725,9.915 ; C28.2@15.9,20.8 15.9,20.78 16.238,20.442 16.238,19.874 v1(16.278,19.834) ; R620.1@16.725,9.925 R620.1@16.725,9.915 ; v1(17.35,9.85) 17.294,9.85 17.239,9.905 16.735,9.905 R620.1@16.725,9.915 ; v1(18.15,8.25) 18.175,8.225 18.175,7.385 P900.B1_A12@18.2,7.36 ; U9.1@20.875,29.35 20.921,29.396 20.921,30.013 v1(20.96,30.052) ; C35.2@23.404,28.714 23.414,28.704 23.414,28.451 23.55,28.315 23.91,28.315 v1(23.95,28.275)
  Top Layer w0.305: U7.6@0.825,41.75 0.825,44.125 v1(0.975,44.275) U7.6@0.975,42.75 ; U7.6@0.975,42.16 1.01,42.125 1.01,42.1 1.275,42.1 ; 1.175,44.475 U7.7@2.2,44.475 2.2,44.577 3.1,44.577 ; v1@1.9,0.825 2.35,0.825 R26.2@2.375,0.825 ; 2.175,41.4 2.175,41.075 U7.5@2.2,41.05 ; U8.2@2.25,37.3 U8.2@2.25,37.35 2.25,38.425 v1(2.725,38.9) ; C38.2@2.375,3.025 2.375,3.005 2.383,2.997 2.798,2.997 2.995,2.8 v1(3.05,2.8) ; U7.3@2.625,43.425 3.35,43.425 U7.8@3.425,43.5 ; 3.05,42.725 3.875,42.725 3.9,42.75 ; U7.8@3.425,42.75 U7.8@3.425,43.5 ; v1(3.451,38.91) v1@3.458,38.917 ; v1@4.05,43.825 3.995,43.825 3.918,43.748 3.46,43.748 3.425,43.713 U7.8@3.425,43.5 ; C36.2@4.217,38.917 C36.2@4.225,38.925 ; C907.2@6.735,27.653 6.982,27.406 7.238,27.406 7.559,27.084 ; v1(7.625,26.701) 7.664,26.74 7.664,26.979 7.559,27.084 ; C924.2@8.174,27.363 8.174,27.343 8.166,27.336 7.811,27.336 7.559,27.084 ; C16.2@8.274,31.297 C16.2@8.282,31.289 ; C16.2@8.282,31.308 C16.2@8.274,31.317 C16.2@8.274,31.317 8.274,31.323 8.282,31.33 8.699,31.33 v1(8.712,31.344) v1@8.7,31.356 ; v1(10.125,27) 10.125,27.775 10.127,27.777 10.127,27.802 10.375,28.05 C8.2@10.4,28.05 10.525,28.175 11.4,28.175 C20.2@11.506,28.281 ; C925.2@11.321,26.179 11.821,26.179 12,26.357 C926.2@12,27.425 11.98,27.425 11.972,27.433 11.972,27.828 11.525,28.275 C20.2@11.525,28.3 ; C20.2@11.525,28.262 C20.2@11.506,28.281 ; C20.2@11.558,28.267 C20.2@11.525,28.3 ; R1.1@12.125,22.825 12.581,22.825 12.687,22.719 12.687,22.698 12.854,22.532 v1(12.854,22.477) ; C15.2@14.025,30.025 14.045,30.025 14.267,29.803 14.267,29.77 14.565,29.473 14.673,29.473 C14.2@14.77,29.375 14.868,29.473 15.143,29.473 15.315,29.645 v1(15.328,29.645) ; X1.2@15.839,35.039 X1.2@15.875,35.075 ; v1@18.244,25.593 v1(18.299,25.593) ; v1(18.371,24.242) 18.371,24.187 18.536,24.022 18.536,23.811 C26.2@18.544,23.803 ; v1(18.701,19.465) 18.729,19.494 19.069,19.494 19.217,19.642 20.447,19.642 P1.2@20.665,19.86 ; P1.2@21.015,19.86 21.226,19.649 22.302,19.649 22.359,19.592 v1(22.414,19.592) ; v1(25.15,1.7) 25.15,1.775 25.475,2.1 U10.2@25.775,2.1 ; 26.275,41.75 U11.6@26.95,41.75 ; v1(26.4,42.8) 26.925,42.8 U11.6@26.975,42.75 27,42.775 27.375,42.775 ; 26.65,44.025 U11.6@26.925,43.75 ; U11.5@27.7,41.025 U11.5@28.2,41.025 28.575,41.025 v1(28.975,40.625) ; 27.85,44.154 27.85,44.465 27.86,44.475 U11.7@28.2,44.475 29.175,44.475 v1(29.425,44.225) v1@29.425,44.17 ; 29.104,42.125 29.39,42.125 29.425,42.16 U11.8@29.425,42.75 v1@29.425,44.17 ; v1(29.577,3.21) 29.577,3.155 29.753,2.979 29.753,2.684 C37.2@29.761,2.676 ; 29.625,41.568 29.625,43.97 v1@29.425,44.17 ; C20.2@11.506,28.281 C20.2@11.525,28.3
  Top Layer w0.5: C7.2@8,29.925 8.025,29.925 8.279,30.179 8.279,30.707 v1(8.28,30.709)
  Top Layer w0.508: v1(15.08,35.14) 15.51,35.14 X1.2@15.675,34.975 ; X1.2@15.737,35.14 X1.2@15.839,35.039 ; X1.4@16.825,36.375 X1.4@16.875,36.425 ; X1.4@16.825,36.425 X1.4@16.875,36.425 ; X1.4@16.923,36.473 X1.4@16.875,36.425 ; v1(17.824,36.473) 17.776,36.425 X1.4@16.875,36.425
  Top Layer w0.6: v1(13.156,44.378) 13.244,44.466 ANT1.4@13.972,44.466 ; ANT1.2@16.972,43.166 17.711,43.166 v1(17.751,43.206) ; ANT1.3@16.972,44.466 17.709,44.466 v1(17.775,44.4)
  Signal Layer 2 w0.305: v1(23.382,9.61) 23.404,9.587 24.093,9.587 24.95,8.73 24.95,6.425 26.3,5.075 26.8,5.075 27.325,4.55 27.325,3.21 ; v1(25.15,1.7) 26.6,3.15 27.325,3.15 27.325,3.21 ; v1(29.577,3.21) 27.325,3.21
  Signal Layer 3 w0.305: v1@29.526,3.15 v1@29.55,3.127
  Signal Layer 4 w0.305: v1(0.9,3.152) v1(0.9,4.452) v1(0.9,5.752)
  Signal Layer 6 w0.3: v1(17.35,9.85) v1@17.375,9.825
  Bottom Layer w0.102: U903.1@18.625,27.55 18.1,27.55 17.95,27.7 17.95,27.95 ; U903.2@18.625,28.05 18.05,28.05 ; U903.3@18.625,28.55 18.076,28.55 ; U903.4@18.624,29.049 18.01,29.049 17.95,28.99 17.95,28.77 17.95,28.676 ; U2.12@22.918,34.025 U2.12@22.985,34.025 ; 17.95,27.95 17.95,28.05 ; 17.95,27.95 18.05,28.05 ; 17.95,28.05 18.05,28.05 ; 17.95,28.05 17.95,28.15 ; 17.95,28.15 17.95,28.425 ; 17.95,28.15 18.05,28.05 ; 17.95,28.425 17.95,28.55 ; 17.95,28.425 18.075,28.55 ; 17.95,28.55 18.075,28.55 ; 17.95,28.55 17.95,28.676 ; 17.95,28.676 18.076,28.55 ; 18.075,28.55 18.076,28.55
  Bottom Layer w0.2: U900.C8@7.25,25 7.316,25 7.41,25.094 7.418,25.094 7.656,25.332 7.656,25.527 7.768,25.639 v1(7.768,25.69) ; U900.C5@7.25,26.5 7.325,26.5 7.487,26.662 7.636,26.662 v1@7.675,26.701 ; U900.H3@9.75,27.5 U900.J3@10.25,27.5 10.25,27.125 v1(10.125,27) ; v1@10.15,24.05 v1(10.2,24.05) 10.3,24.05 10.75,23.6 U900.K11@10.75,23.5 U900.K12@10.75,23 ; v1(10.795,26.22) 11.22,26.22 11.25,26.25 ; U900.L6@11.25,26 11.25,26.25 ; U900.L5@11.25,26.5 11.25,26.25 ; U900.M11@11.75,23.5 U900.N12@12.25,23 12.774,22.476 v1@12.774,22.451 ; U900.M8@11.75,25 U900.N8@12.25,25 U900.N8@12.252,25.002 ; U900.N8@12.253,25.002 12.595,25.344 v1(12.678,25.344) ; v1@12.776,22.451 12.776,22.368 13.083,22.061 13.083,22.042 13.2,21.925 13.502,21.925 C904.2@13.506,21.921 ; C24.2@19.15,31.97 C24.2@19.15,31.95 19.166,31.966 19.553,31.966 v1(19.569,31.982) ; U2.7@22.3,35.71 22.3,35.95 22.481,36.131 22.481,36.369 22.706,36.595 v1(22.706,36.678) ; C32.2@28.745,41.692 28.749,41.696 28.749,42.225 C33.2@28.752,42.228
  Bottom Layer w0.203: R934.2@5.992,35.027 6.051,35.085 R934.2@6.061,35.085 R934.2@6.063,35.088 ; v1@6.645,35.088 v1(6.647,35.091) ; v1(18.95,36.425) 18.95,36.343 19.198,36.094 19.198,35.712 U6.7@19.2,35.71
  Bottom Layer w0.25: v1(5.616,40.079) 5.783,40.245 6.12,40.245 C916.2@6.125,40.25 6.175,40.3 U902.3@6.175,41
  Bottom Layer w0.254: v1@4.439,28.036 4.439,27.783 4.5,27.722 U901.B2@4.5,27.4 ; C915.2@4.85,39.325 5.012,39.163 5.012,38.649 ; U904.2@5.475,33.825 5.477,33.823 5.477,33.398 5.666,33.209 v1(6.559,33.209) 6.511,33.16 6.511,32.932 5.975,32.396 U904.4@5.975,32.325
  Bottom Layer w0.3: v1@4.036,42.035 4.059,42.035 4.069,42.025 4.071,42.027 4.073,42.025 4.25,42.202 R909.1@4.25,42.7 ; v1@6.559,33.153 v1(6.559,33.209) ; v1(7.525,41.775) 7.525,41.831 7.629,41.935 7.629,42.054 7.975,42.4 C917.2@8.475,42.4 ; v1(10.098,20.546) 10.129,20.577 10.129,21.058 C900.2@10.16,21.089 ; C24.2@19.15,31.97 C24.2@19.154,31.966 ; v1(20.96,30.052) 20.989,30.024 20.989,29.695 20.999,29.685 C23.2@21.017,29.685 ; U5.7@22.35,32.425 22.476,32.425 22.552,32.502 22.602,32.502 22.879,32.779 22.879,32.985 v1(22.919,33.025) 22.862,33.025 22.783,33.105 22.469,33.105 C22.2@22.459,33.115 ; v1(22.409,22.031) 22.449,22.071 22.449,22.16 22.8,22.511 TPJ13.1@22.8,22.7
  Bottom Layer w0.305: v1(0.975,44.275) 1.014,44.236 1.014,43.671 1.746,42.939 C31.2@2.599,42.939 2.903,42.635 2.903,42.308 2.91,42.3 C30.2@2.921,42.3 C29.2@2.921,41.754 ; v1(3.16,23.6) 3.215,23.6 3.437,23.822 C901.2@4.824,23.822 ; v1(3.875,21.025) 3.875,20.65 4.075,20.45 4.608,20.45 C902.2@4.625,20.433 C902.2@4.6,20.433 ; C910.2@3.919,25.286 3.919,25.266 3.927,25.258 4.248,25.258 4.417,25.089 v1(4.454,25.089) ; C914.2@4.267,28.571 4.287,28.571 4.295,28.563 4.295,28.26 4.352,28.203 4.352,28.124 v1(4.391,28.085) ; C915.2@5.012,39.163 5.098,39.077 5.098,38.879 5.276,38.7 5.475,38.7 5.902,38.273 6.176,38.273 6.183,38.266 R933.2@6.183,38.256 ; Q902.1@5.45,36.075 5.452,36.073 5.452,35.723 5.676,35.499 5.712,35.499 5.885,35.327 5.885,35.251 R934.2@6.051,35.085 ; C918.2@5.509,44.05 5.529,44.05 5.536,44.058 5.536,44.428 5.6,44.491 v1(5.6,44.546) ; R934.2@6.063,35.088 v1@6.645,35.088 ; C911.2@8.239,21.014 8.259,21.014 8.634,20.639 8.634,20.511 v1(8.673,20.472) ; v1@8.738,31.267 8.992,31.013 C908.2@8.992,30.048 ; C923.2@12.548,19.232 12.548,19.212 12.555,19.205 12.575,19.205 12.577,19.202 v1(13.056,19.202) ; v1(12.678,25.344) 12.717,25.305 13.795,25.305 X900.2@14,25.1 ; v1@12.774,22.451 12.776,22.451 12.828,22.451 v1(12.854,22.477) ; 14.066,20.417 14.12,20.363 14.12,19.955 14.128,19.947 C909.2@14.148,19.947 ; C909.2@14.168,19.947 C909.2@14.148,19.947 ; v1@14.374,20.286 v1(14.413,20.324) 14.358,20.324 14.179,20.146 14.15,20.146 14.15,19.949 C909.2@14.148,19.947 ; X900.4@15.1,23.7 15.1,22.125 15.493,21.732 v1(16.332,21.732) ; R208.1@18.158,20.657 18.191,20.623 18.191,20.059 v1(18.225,20.025) ; R208.1@18.184,20.657 R208.1@18.205,20.636 ; R208.1@18.2,20.7 18.265,20.635 19.114,20.635 Q200.1@19.116,20.633 Q200.1@18.971,20.633 ; v1@18.31,24.203 18.36,24.253 v1(18.371,24.242) 18.465,24.148 18.465,23.948 18.662,23.751 C39.2@18.662,23.731 ; U903.4@18.575,29.075 C919.2@18.575,29.775 18.595,29.775 18.603,29.783 18.603,30.05 19.029,30.477 v1(19.029,30.532) ; v1(22.919,33.025) U2.12@22.919,33.926 ; v1(26.4,42.8) 26.475,42.875 C34.2@28.35,42.875 28.75,42.475 C33.2@28.75,42.25 ; C32.2@28.745,41.692 28.75,41.688 28.75,40.85 v1(28.975,40.625)
  Bottom Layer w0.4: D902.3@24.075,20.3 24.075,19.137 v1(24.077,19.134)
  Bottom Layer w0.508: C920.2@8.2,39.4 8.2,39.667 v1(8.716,40.183)
  Bottom Layer w0.635: v1(2.725,38.9) 3.082,38.9 3.094,38.912 3.451,38.912 v1(3.451,38.91) ; v1@3.462,38.912 3.767,39.217 4.768,39.217 4.85,39.3 C915.2@4.85,39.325 4.85,39.35 5.579,40.079 v1(5.616,40.079) ; 5.354,42.5 5.357,42.503 ; v1(7.525,41.775) U902.9@6.8,41.775 ; v1@7.525,41.831 v1@7.525,42.4 ; v1(7.525,42.575) 5.429,42.575 5.357,42.503 ; 7.975,42.4 v1@7.525,42.4 ; v1(23.8,18.339) 24.008,18.131 24.008,17.425 ; C921.2@23.85,16.65 24.008,16.808 24.008,17.425 ; 24.1,17.75 24.1,17.517 24.008,17.425 ; 5.357,41.782 5.357,42.503 ; 5.357,41.782 5.365,41.775 U902.9@6.8,41.775 ; 5.357,41.782 5.725,42.15 U902.9@6.425,42.15 ; U902.9@6.425,42.15 6.675,42.4 v1@7.525,42.4 ; U902.9@6.425,42.15 U902.9@6.8,41.775
  Bottom Layer w1.27: P901.2@15,7.5 15.061,7.439 v1(15.061,4.975) 15.061,3.889 15.55,3.4
  other v1: 10.363,0.864 12.568,0.863 1.9,0.875 4.2,0.875 5.6,0.875 6.7,0.875 8.5,0.875 14.925,0.875 17.7,0.9 1.1,1 0.9,1.852 5.925,2.1 9.15,2.575 6.2,2.875 16.375,2.925 13.75,2.95 8.225,4.525 12.373,5.008 17.577,5.105 13.95,6.4 16.217,6.388 8.625,7.975 6.375,8.2 16.124,8.479 10.908,8.574 0.9,8.6 23.197,8.775 28.6,8.8 29.5,8.852 10.126,9.142 21.075,9.175 7.166,9.227 19.25,9.5 0.9,9.652 29.5,9.652 22.125,9.725 11.825,10.834 20.625,10.85 16.763,10.888 9.715,10.954 13.712,10.959 18.47,11.031 28.828,11.06 23.961,11.327 8.542,11.346 15.758,11.512 0.9,11.652 6.483,12.458 11.825,12.598 9.797,12.63 15.125,12.632 10.729,12.649 23.838,12.919 5.1,13.375 0.9,13.435 6.95,13.5 29.274,13.551 0.9,14.105 7.397,14.508 8.977,14.797 11.956,14.843 0.9,15.975 8.95,16.25 0.9,16.645 20.708,16.739 16.071,16.799 12.585,16.83 8.15,16.925 29.422,17.032 0.9,18.515 0.9,19.185 17.386,19.271 29.363,19.807 0.9,21.055 29.445,21.327 0.9,21.725 11.178,21.902 0.9,23.595 29.475,23.725 0.9,24.265 29.475,24.575 0.9,26.135 29.472,26.135 0.9,26.805 29.472,26.805 12.843,26.846 19.546,27.163 0.9,28.675 29.472,28.675 0.9,29.345 29.472,29.345 0.9,31.215 29.472,31.215 0.9,31.885 29.472,31.885 10.275,32.35 11.075,32.35 11.875,32.35 12.675,32.35 13.475,32.35 10.275,33.15 11.075,33.15 11.875,33.15 12.675,33.15 0.9,33.755 29.472,33.755 10.275,33.95 11.075,33.95 11.875,33.95 12.675,33.95 0.9,34.425 29.472,34.425 26.137,34.646 10.275,34.75 11.075,34.75 11.875,34.75 12.675,34.75 13.475,34.75 11.075,35.55 11.875,35.55 12.675,35.55 13.475,35.55 0.9,36.252 29.5,36.252 3.726,36.397 25.25,36.775 23.876,37.059 27.175,37.175 11.28,38.285 15.467,38.406 17.653,38.405 16.224,38.42 16.938,38.415 24.698,38.6 23.273,38.625 19.075,38.65 20.5,38.65 21.848,38.65 10.528,38.916 13.2,39.4 29.5,39.552 24.698,39.676 17.751,39.701 19.075,39.701 20.5,39.701 21.848,39.701 23.273,39.701 10.6,39.725 13.203,40.325 11.1,40.525 17.751,40.895 19.075,40.895 20.5,40.895 21.848,40.895 11.75,41.15 13.226,41.302 4.061,42.06 17.751,42.063 19.075,42.063 20.5,42.063 13.22,42.122 11.728,42.343 19.075,43.206 20.5,43.206 11.751,43.319 24.875,43.506 12.526,43.748 4.2,43.875 10.881,43.977 19.1,44.4 20.525,44.4 21.975,44.4 23.425,44.4 24.875,44.4 26.325,44.4 11.664,44.482 10.011,44.509 8.704,44.525
  other v2: 13.159,37.57 13.954,38.411 14.791,38.42 13.188,38.51 11.85,39.024 11.475,39.424 11.85,39.824 10.483,41.263 9.231,41.973 10.533,42.722 9.268,43.492 7.198,44.541
IMU_SPI_CIPO: U4.9 U6.3 | length 28.8
  Top Layer w0.102: U4.9@15.4,22.53 15.4,22.375 15.4,20.252 15.644,20.007 v1(15.644,19.921)
  Signal Layer 3 w0.102: v1(15.644,19.921) 15.7,19.977 15.7,21.675 16.276,22.25 16.95,22.25 17.7,23 17.7,26.125 15.74,28.085 15.74,30.635 15.309,31.066 15.309,32.4 15.543,32.635 15.926,32.635 16.286,32.995 16.67,32.995 16.782,33.107 16.782,33.668 18.275,35.162 18.275,37.837 18.466,38.028 v1(18.466,38.1)
  Bottom Layer w0.102: U6.3@17.805,34.825 17.417,35.213 17.417,36.779 18.417,37.778 18.417,38.051 v1(18.466,38.1)
IMU_SPI_COPI: U4.24 U6.1 | length 10.4
  Top Layer w0.102: U4.24@14.4,26.47 14.403,26.473 14.403,27.147 v1(14.406,27.15)
  Signal Layer 5 w0.102: v1(14.406,27.15) 14.406,27.219 14,27.625 14,30.725 14.55,31.275 15.975,31.275 17.943,33.243 17.943,33.56 v1(17.989,33.606)
  Bottom Layer w0.102: U6.1@17.805,34.025 17.976,34.025 17.989,34.012 v1(17.989,33.606)
IMU_SPI_CS: R13.2 U4.22 U6.11 | length 13.9
  Top Layer w0.102: U4.22@15.4,26.325 15.4,26.619 15.46,26.678 18.649,26.678 18.756,26.571 18.8,26.571 19.075,26.296 19.075,26.25 19.156,26.169 19.156,26.159 19.265,26.05 R13.2@19.275,26.05
  Signal Layer 3 w0.102: v1(18.878,26.559) 18.858,26.579 18.858,29.233 19.544,29.918 19.544,31.256 19.975,31.688 19.975,32.378 19.644,32.709 v1(19.644,33.526)
  Bottom Layer w0.102: v1(19.644,33.526) 19.644,33.534 19.882,33.773 20.276,33.773 20.377,33.874 20.377,34.176 20.276,34.277 20.273,34.277 20.125,34.425 U6.11@19.819,34.425
IMU_SPI_SCLK: U4.23 U6.8 | length 14.4
  Top Layer w0.102: U4.23@14.9,26.325 14.9,26.751 15.664,27.514 v1(16.999,27.514)
  Signal Layer 3 w0.102: v1(16.999,27.514) 16.999,27.576 17.2,27.777 17.2,31.267 18.444,32.511 19.173,32.511 19.381,32.719 19.381,33.143 19.334,33.19 19.334,33.194 19.221,33.307 19.221,33.988 19.567,34.335 v1(19.567,36.53)
  Bottom Layer w0.102: v1(19.567,36.53) 19.575,36.522 U6.8@19.575,35.625
MIC_PDM_CLK: U5.3 U7.2 U11.2 | length 46
  Top Layer w0.102: U7.2@1.775,43.425 1.775,43.675 2.175,44.075 2.819,44.075 3.015,44.272 v1(3.553,44.272) ; v1@27.176,44.277 27.775,43.678 U11.2@27.775,43.425
  Signal Layer 4 w0.102: v1(3.553,44.272) 3.553,43.802 6.028,41.328 6.028,39.872 6.702,39.198 9.216,39.198 10.371,38.042 10.371,37.124 11.103,36.392 13.875,36.392 14.37,35.897 14.37,35.115 15.183,34.302 21.686,34.302 21.862,34.125 23.7,34.125 26,36.425 26,40.775 27.176,41.951 v1@27.176,44.277
  Signal Layer 5 w0.102: v1(21.934,31.307) 22.45,31.823 22.45,33.325 23.25,34.125 v1@23.7,34.125
  Bottom Layer w0.102: U5.3@21.215,31.35 21.925,31.35 21.909,31.366 v1@21.909,31.407
  other v1: 23.7,34.15 27.201,44.252
MIC_PDM_DATA: R17.2 R24.2 U5.8 | length 36.6
  Signal Layer 4 w0.102: v1(3.975,40.8) 5.1,40.8 5.21,40.69 5.21,39.89 5.375,39.725 6.179,38.921 9.122,38.921 10.075,37.967 10.075,37.132 11.018,36.189 13.775,36.189 13.989,35.975 14,35.975 14.15,35.825 14.15,34.982 15.033,34.099 21.501,34.099 22.475,33.125 22.475,32.825 22.673,32.627 22.692,32.627 22.7,32.619 23.366,32.619 v1@23.399,32.652 ; v1(23.424,32.627) 23.94,32.627 24.867,33.553 24.867,34.849 26.289,36.271 26.289,39.864 v1(26.575,40.15)
  Bottom Layer w0.102: R17.2@2.4,41.225 3.55,41.225 v1(3.975,40.8) ; U5.8@22.985,32.15 23.225,32.15 23.374,32.299 v1@23.374,32.627 ; v1(26.575,40.15) R24.2@26.575,40.675
N16783896: R908.1 R909.2 U902.5 | length 1.3
  Bottom Layer w0.127: R909.2@4.325,43.3 U902.5@5.675,43.3
N16783941: R907.1 U902.7 | length 0.8
  Bottom Layer w0.127: U902.7@6.675,43.3 6.675,43.825 6.794,43.944 6.794,43.954 6.89,44.05 R907.1@6.9,44.05
N16783963: C918.1 U902.6 | length 0.8
  Bottom Layer w0.102: C918.1@6.059,44.05 6.066,44.05 6.175,43.941 U902.6@6.175,43.3
N16784651: Q901.2 Q901.5 R915.2 R938.1 | length 4.3
  Top Layer w0.203: R938.1@7.019,35.962 7.026,35.968 7.568,35.968 R915.2@7.575,35.975 7.575,35.965 7.517,35.907 7.517,35.717 7.364,35.565 7.364,35.076 v1(7.305,35.017)
  Bottom Layer w0.1: Q901.2@7.65,35.762 7.65,36.332 7.653,36.334 7.653,36.903 7.65,36.906 Q901.5@7.65,37.587
  Bottom Layer w0.203: v1(7.305,35.017) 7.364,35.076 7.364,35.464 7.602,35.702 7.602,35.714 Q901.2@7.65,35.762
N16784657: C921.1 P901.1 Q901.3 Q901.8 | length 78.4
  Signal Layer 5 w0.635: v1(4.228,10.046) 4.243,10.061 v1(5.167,10.061) 5.961,10.061 10.025,14.125 10.025,18 6.798,21.227 6.798,28.62 6.005,29.413 5.56,29.413 5.096,29.877 5.096,31.079 5.604,31.587 5.604,34.613 5.911,34.92 5.911,35.49 v1(6.262,35.841) 6.217,35.885 v1(6.217,36.525)
  Signal Layer 6 w0.635: v1(4.228,10.046) 4.243,10.061 v1(5.167,10.061) 5.167,10.167 8.386,13.386 20.764,13.386 23.7,10.45 v1(25.755,10.45) ; v1@25.775,10.45 25.779,10.446 v1(26.648,10.446)
  Bottom Layer w0.203: v1(6.262,35.841) 6.32,35.782 6.403,35.782 6.423,35.762 Q901.3@7,35.762
  Bottom Layer w0.635: P901.1@4.41,9.762 P901.1@4.063,9.415 ; 4.717,10.061 4.702,10.046 v1(4.228,10.046) 4.228,9.579 P901.1@4.063,9.415 ; v1(5.167,10.061) 5.016,10.061 4.717,9.762 4.717,8.168 4.063,7.515 P901.1@4.063,9.415 ; v1(6.217,36.525) 6.217,35.885 v1(6.262,35.841) ; v1@6.222,36.52 6.24,36.503 6.804,36.503 6.819,36.517 7.173,36.517 7.184,36.528 Q901.8@7.184,36.675 ; P901.1@24.974,5.3 P901.1@25.299,5.625 ; C921.1@25.45,16.65 25.45,14.8 26.143,14.107 26.143,10.45 ; P901.1@25.922,7.5 25.922,8.335 25.755,8.502 v1(25.755,10.45) 26.143,10.45 ; v1(26.648,10.446) 26.644,10.45 26.143,10.45 ; P901.1@26.812,8.9 P901.1@27.3,8.9
  other v1: 3.3,10.025 27.525,10.45
N16820078: L1.1 U1.14 | length 1.8
  Top Layer w0.22: U1.14@12.475,36.445 L1.1@12.475,38.25
N16820097: C2.1 L1.2 L2.1 | length 1.1
  Top Layer w0.2: L1.2@12.475,38.85 L2.1@12.475,39.95
N16820130: C4.1 CC1.2 L9.1 | length 1.4
  Top Layer w0.2: CC1.2@12.475,41.7 L9.1@12.475,43.05
N16820670: C11.1 C12.1 L4.2 U1.12 | length 2.6
  Top Layer w0.22: U1.12@13.275,36.445 13.275,36.914 13.536,37.175 C11.1@13.925,37.175 14.855,37.175 15.18,37.5 L4.2@15.205,37.5
N16820694: C18.1 C19.1 L5.2 U1.15 | length 3.2
  Top Layer w0.2: L5.2@9.992,37.9 10.017,37.9 10.142,37.775 C18.1@10.54,37.775 10.54,37.772 10.6,37.712 11.623,37.712 11.658,37.677 11.74,37.677 11.8,37.617 11.8,37.089 12.065,36.824 12.065,36.455 U1.15@12.075,36.445
N16821218: C16.1 U1.30 | length 1.2
  Top Layer w0.2: C16.1@8.274,31.867 8.3,31.892 8.622,31.892 8.879,32.15 U1.30@9.38,32.15
N16822182: C20.1 C21.1 R6.2 U1.35 | length 4.7
  Top Layer w0.203: U1.35@11.675,31.455 11.683,31.447 11.683,31.064 11.857,30.891 12.192,30.556 12.192,30.258 C21.1@12.25,30.2 12.278,30.172 C21.1@12.403,30.172
  Top Layer w0.305: C21.1@12.25,30.2 12.25,30.18 C21.1@12.258,30.172 ; C21.1@12.403,30.172 12.9,29.676 12.9,28.325 C20.1@12.925,28.3 12.959,28.334 13.821,28.334 R6.2@13.829,28.341
N16822845: R1.2 SW1.3 SW1.4 | length 5.5
  Top Layer w0.102: SW1.3@6.9,22.875 11.258,22.875 11.532,23.149 11.541,23.149 11.816,23.425 R1.2@12.125,23.425
N16851259: R26.1 SW2.3 SW2.4 | length 5.2
  Top Layer w0.102: R26.1@2.375,1.425 SW2.3@3.375,1.425 SW2.4@7.525,1.425
N16851354: LED1.1 R27.2 | length 0.8
  Top Layer w0.12: LED1.1@17.741,28.6 17.891,28.45 R27.2@18.425,28.45
  Top Layer w0.305: R27.2@18.407,28.468 R27.2@18.417,28.468
N16942953: C28.1 U4.10 | length 1.2
  Top Layer w0.2: C28.1@15.9,21.35 15.877,21.373 15.877,21.921 15.9,21.944 U4.10@15.9,22.53
N16944331: R22.2 TP1.1 U9.3 | length 13
  Top Layer w0.3: v1(20.609,27.023) 20.609,27.079 20.875,27.345 U9.3@20.875,28.05
  Signal Layer 6 w0.305: v1(20.609,27.023) 20.609,27.006 21.148,26.467 22.018,26.467 23.676,26.467 v1@24.438,27.229 ; v1(24.46,27.229) 24.879,27.229 25.008,27.1 25.322,27.1 ; v1(25.6,26.225) 25.6,26.822 ; v1@26.6,27.1 25.878,27.1 ; 25.322,27.1 25.6,27.1 ; 25.322,27.1 25.6,26.822 ; 25.6,26.822 25.6,27.1 ; 25.6,26.822 25.878,27.1 ; 25.6,27.1 25.878,27.1
  Bottom Layer w0.3: R22.2@20.549,26.487 20.559,26.497 20.559,26.916 20.609,26.966 v1(20.609,27.023)
  Bottom Layer w0.305: v1@24.55,27.1 TP1.1@25.6,27.1 ; TP1.1@25.467,26.967 TP1.1@25.6,27.1 ; v1@25.6,26.25 TP1.1@25.6,27.1 ; v1@26.6,27.1 TP1.1@25.6,27.1
  other v1: 26.65,27.1
N16944525: R23.2 TP2.1 U8.5 | length 3.1
  Top Layer w0.3: U8.5@1.3,39.625 1.3,39.55 U8.5@1.375,39.625 ; U8.5@1.3,39.7 U8.5@1.375,39.625 ; U8.5@1.4,39.6 U8.5@1.375,39.625 ; v1(1.925,39.6) 1.885,39.64 1.39,39.64 U8.5@1.375,39.625
  Bottom Layer w0.3: TP2.1@1.111,40.1 TP2.1@1.3,40.1 ; TP2.1@1.3,39.911 TP2.1@1.3,40.1 ; TP2.1@1.525,40.1 TP2.1@1.425,40.1 ; R23.2@2.4,40.25 2.39,40.25 2.205,40.065 2.205,39.904 1.925,39.624 v1(1.925,39.6) TP2.1@1.425,40.1 ; TP2.1@1.3,40.1 TP2.1@1.425,40.1
N16945514: C32.1 C33.1 C34.1 R20.1 U11.3 U11.4 | length 5
  Top Layer w0.3: U11.3@28.625,43.425 U11.4@28.625,42.075 28.625,41.85 v1(29.3,41.175)
  Bottom Layer w0.3: R20.1@29.15,43.525 29.15,43.025 C34.1@29.3,42.875 ; v1(29.3,41.175) 29.298,41.177 29.298,41.69 C32.1@29.295,41.692 29.299,41.696 29.299,42.225 C33.1@29.302,42.228 29.302,42.827 C34.1@29.35,42.875
N16945580: C29.1 C30.1 C31.1 R15.1 U7.4 | length 4.3
  Top Layer w0.3: U7.4@2.625,42.075 2.625,41.759 3.065,41.319 v1@3.831,41.319
  Bottom Layer w0.3: C30.1@3.5,42.3 3.485,42.3 3.475,42.29 C29.1@3.475,41.75 3.8,41.425 v1(3.975,41.425) ; C30.1@3.501,42.301 3.501,42.434 3.53,42.464 3.53,42.869 C31.1@3.599,42.939
  Bottom Layer w0.305: C31.1@3.499,42.939 C31.1@3.549,42.989 ; C31.1@3.55,42.975 R15.1@3.55,43.65
N17008241: C900.1 U900.J13 | length 2
  Bottom Layer w0.203: C900.1@9.16,21.089 9.664,21.593 9.814,21.593 10.25,22.028 U900.J13@10.25,22.5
